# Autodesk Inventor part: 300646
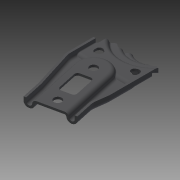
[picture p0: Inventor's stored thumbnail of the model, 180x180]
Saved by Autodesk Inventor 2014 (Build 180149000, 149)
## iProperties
Created: 2007-12
Part Number: 300646
Document SubType Name: Modeling
Designer: MM
Density: 7.85 g/cm^3
Mass: 265.832 g
Surface Area: 247.186 cm^2
Volume: 33.864 cm^3
Material: Steel
Description: LEFT SIDE SPRING BRACKET
Appearance: Gray
Component Category: Back Component
Author: MM
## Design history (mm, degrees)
node "301231" dims "d0" = 10
body "Solid1"
tag "TaggingFeature2"
feature "DerivedBody::D-301231" dims "d0" = 10
